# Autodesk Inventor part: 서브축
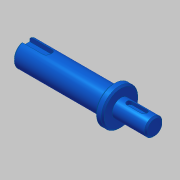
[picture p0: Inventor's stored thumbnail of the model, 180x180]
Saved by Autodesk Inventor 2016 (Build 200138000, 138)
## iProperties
Created: 2018-09
Part Number: 서브축
Document SubType Name: Modeling
Density: 7.86 g/cm^3
Material: 강철, 연강
Appearance: 청록색
Mass: 142.801 g
Surface Area: 54.794 cm^2
Volume: 18.1681 cm^3
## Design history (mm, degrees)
sketch "스케치1"
  geometry: L1 (-18.818, -7)-(-18.818, 7) reference; L2 (-41.331, -13.5)-(-41.331, 13.5) reference; L3 (-46.5, 12.249)-(-46.5, -12.249) reference; L4 (-18.331, 0)-(-106.5, 0); L5 (-18.331, 0)-(-18.331, -6); L6 (-18.331, -6)-(-41.331, -6); L7 (-41.331, -12.5)-(-46.5, -12.5); L8 (-46.5, -8.5)-(-106.5, -8.5); L9 (-106.5, -8.5)-(-106.5, 0); L10 (-46.5, -8.5)-(-46.5, -12.5); L11 (-41.331, -6)-(-41.331, -12.5); 2 further points
  constraints: 17 end point, 5 point on line, 3 parallel, 3 perpendicular, 2 collinear, 1 midpoint
  dimensions: "d0" = 23 distance between parallel lines of L2 L5; "d1" = 12 diameter of L6 L4; "d2" = 25 diameter of L7 L4; "d3" = 17 diameter of L8 L4; "d4" = 60 distance of L8.start L8.end
revolve "회전1" sketch "스케치1" stored, may be unused: angle "d5" = 90 deg
chamfer "모따기1" distance "d6" = 1; stored, may be unused: second distance "d7" = 2, angle "d8" = 45 deg
node "작업 평면1"
sketch "스케치2"
  geometry: L1 (11.5, 5)-(11.5, -5) reference; L2 (-5.5, -2)-(4.5, -2); L3 (4.5, 2)-(-5.5, 2); A1 r 2 centre (4.5, 0) between (4.5, -2) and (4.5, 2); A2 r 2 centre (-5.5, 0) between (-5.5, 2) and (-5.5, -2); 2 further points
  constraints: 4 end point, 4 point on circle, 4 tangent, 2 centre point, 1 horizontal alignment, 1 midpoint, 1 parallel, 1 perpendicular
  dimensions: "d9" = 4 distance between parallel lines of L2 L3; "d10" = 14 dimension on A1 A2; "d11" = 5 distance edge to line of A1 L1
extrude "돌출1" cut sketch "스케치2" distance "d12" = 2.5; taper "d13" = 0 deg
node "작업 평면2"
sketch "스케치3"
  geometry: L1 (-30, -7.5)-(-30, 7.5) reference; L2 (-30, 3)-(-15, 3); L3 (-15, -3)-(-30, -3); A1 r 3 centre (-15, 0) between (-15, -3) and (-15, 3); 2 further points
  constraints: 4 end point, 2 perpendicular, 2 point on circle, 2 point on line, 2 tangent, 1 centre point, 1 horizontal alignment, 1 midpoint
  dimensions: "d14" = 6 distance between parallel lines of L3 L2; "d15" = 18 dimension on A1 L1
extrude "돌출2" cut sketch "스케치3" distance "d16" = 3.5; taper "d17" = 0 deg
node "솔리드1"
node "참조1"
node "참조2"
node "참조3"
